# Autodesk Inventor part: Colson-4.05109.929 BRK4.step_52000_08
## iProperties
Created: 2010-10
Part Number: Colson-4.05109.929 BRK4.step_52000_08
Document SubType Name: Modeling
Designer: Administrator
Density: 7.85 g/cm^3
Material: Steel
Mass: 66.3392 g
Surface Area: 66.9425 cm^2
Volume: 8.45085 cm^3
Author: Administrator
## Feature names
1. Base1
